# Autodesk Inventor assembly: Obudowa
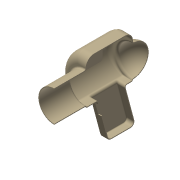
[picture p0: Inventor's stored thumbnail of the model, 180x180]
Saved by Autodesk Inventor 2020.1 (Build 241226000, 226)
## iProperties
Created: 2005-10
Part Number: Obudowa
Document SubType Name: Assembly
Designer: F.Stasiak
Manager: www.cadconsulting.pl
Company: Fabian Stasiak CAD Consulting
Author: F.Stasiak
Subject: Zbiór ćwiczeń. Autodesk Inventor 2020. Kurs podstawowy
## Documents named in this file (2)
- C:\2020_Kurs_podstawowy\R6 Zespoły\Lustro\Obudowa.iam
- C:\2020_Kurs_podstawowy\R6 Zespoły\Lustro\Obudowa_prawa.ipt
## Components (1 placed, 1 different names)
1. Obudowa_prawa:1
